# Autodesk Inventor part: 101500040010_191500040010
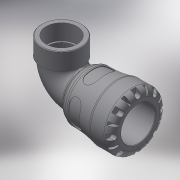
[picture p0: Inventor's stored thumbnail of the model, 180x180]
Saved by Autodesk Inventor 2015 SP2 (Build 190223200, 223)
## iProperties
Created: 2016-12
Part Number: 101500040010_191500040010
Material: Generic
Description: PLASSON 90° ELBOW WITH THREADED FEMALE OFFTAKE 40X1" SERIES 1
Document SubType Name: Modeling
Designer: KIM
Mass: 557.611 g
Surface Area: 990.043 cm^2
Volume: 557.611 cm^3
Density: 1 g/cm^3
Appearance: Default
Author: KIM
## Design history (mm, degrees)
derived "1015.ipt"
feature "Solid1::1015.ipt"
tag "TaggingFeature1"
body "Solid1"
other parameters: "d1" = 30.24, "d8" = 61.6, "d13" = 8, "d14" = 8, "d15" = 0, "d17" = 360 deg, "d19" = 8 deg, "d20" = 0.8, "d21" = 0.8, "d22" = 8 deg, "d24" = 0, "d26" = 360 deg, "d33" = 7, "d43" = 57.4, "d51" = 0.7, "d54" = 14, "d55" = 8.8, "d57" = 15.68, "d58" = 0, "d74" = 0, "d78" = 72, "d82" = 0.8, "d115" = 360 deg, "d207" = 90 deg, "d228" = 11.9, "d247" = 1.4, "d248" = 4.32, "d268" = 33.88, "d269" = 4.32, "d270" = 107, "d279" = 51, "d281" = 4.54365, "d294" = 30.291, "d295" = 21, "d296" = 23.1, "d297" = 27.2619, "d299" = 35.44047, "d300" = 27.2619, "d301" = 0, "d302" = 0, "d303" = 10.97976, "d306" = 8, "d307" = 10.9, "d308" = 8, "d310" = 3, "l_" = 72, "A_" = 107, "A_1" = 51, "l_2" = 21, "Rp_" = 30.291, "d298" = 39.3783
